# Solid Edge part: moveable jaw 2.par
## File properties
Author: CADSoft
Template: Normal.par
Last saved by: Cadcim
Revision: 5
Application: Solid Edge
Accuracy: 0.990
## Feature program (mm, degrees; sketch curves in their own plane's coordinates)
sketch for "unnamed Protrusion 1" plane through (0, 0, 0) normal (0, -1, 0) x-axis (1, 0, 0)
  line (2.077, -7.5) -> (2.077, 52.5)
  line (2.077, 52.5) -> (-32.423, 52.5)
  line (-32.423, 52.5) -> (-32.423, -7.5)
  line (-28.923, -7.5) -> (-32.423, -7.5)
  line (-28.923, -5) -> (-28.923, -7.5)
  line (-28.923, -5) -> (-26.423, -5)
  line (-26.423, -5) -> (-26.423, -2.5)
  line (-26.423, -2.5) -> (-23.923, -2.5)
  line (-23.923, -2.5) -> (-23.923, 0)
  line (-23.923, 0) -> (-21.423, 0)
  line (-21.423, 0) -> (-21.423, 2.5)
  line (-21.423, 2.5) -> (-18.923, 2.5)
  line (-18.923, 2.5) -> (-18.923, 5)
  line (-18.923, 5) -> (-16.423, 5)
  line (-16.423, 5) -> (-16.423, 7.5)
  line (-16.423, 7.5) -> (-15.173, 7.5)
  line (-13.923, 7.5) -> (-15.173, 7.5)
  line (-13.923, 5) -> (-13.923, 7.5)
  line (-11.423, 5) -> (-13.923, 5)
  line (-11.423, 2.5) -> (-11.423, 5)
  line (-8.923, 2.5) -> (-11.423, 2.5)
  line (-8.923, 0) -> (-8.923, 2.5)
  line (-6.423, 0) -> (-8.923, 0)
  line (-6.423, -2.5) -> (-6.423, 0)
  line (-3.923, -2.5) -> (-6.423, -2.5)
  line (-3.923, -5) -> (-3.923, -2.5)
  line (-1.423, -5) -> (-3.923, -5)
  line (-1.423, -5) -> (-1.423, -7.5)
  line (-1.423, -7.5) -> (2.077, -7.5)
extrude "unnamed Protrusion 1" add finite 18 symmetric
sketch for "Hole_1" plane through (-15.173, 0, 52.5) normal (0, 0, 1) x-axis (-1, 0, 0)
  hole centre (0, 0) bore radius 6
hole "Hole_1" diameter 12 finite  VBottomAngle = 120 deg
sketch for "Hole_2" plane through (2.077, 0, 22.5) normal (1, 0, 0) x-axis (0, 1, 0)
  hole centre (0, 23) bore radius 3
hole "Hole_2" diameter 6 through
chamfer "Chamfer_2" setback 2
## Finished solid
Body 1: solid body, 38 faces, 98 edges, 60 vertices.
  Faces by surface: plane 34, cylinder 3, cone 1
  Edges by curve: line 92, circle 4, intersection 2
Bounding box of the edges (mm): 34.500 x 18.000 x 60.000, from (-32.423, -9, -7.5) to (2.077, 9, 52.5).
Cylindrical faces by radius (mm): R3 x2, R6 x1
Conical faces (half-angle, radius in mm at the cone's reference point): 60 deg R6 x1
Planar faces by outward normal: +x 7, +y 1, +z 1, -x 7, -y 1, -z 13, oblique 4
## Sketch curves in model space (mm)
line (-26.423, 0, -5) -> (-26.423, 0, -2.5)
line (-26.423, 0, -2.5) -> (-23.923, 0, -2.5)
line (-23.923, 0, -2.5) -> (-23.923, 0, 0)
line (-23.923, 0, 0) -> (-21.423, 0, 0)
line (-21.423, 0, 0) -> (-21.423, 0, 2.5)
line (-21.423, 0, 2.5) -> (-18.923, 0, 2.5)
line (-18.923, 0, 2.5) -> (-18.923, 0, 5)
line (-18.923, 0, 5) -> (-16.423, 0, 5)
line (-16.423, 0, 5) -> (-16.423, 0, 7.5)
line (-16.423, 0, 7.5) -> (-15.173, 0, 7.5)
line (-13.923, 0, 7.5) -> (-15.173, 0, 7.5)
line (-13.923, 0, 5) -> (-13.923, 0, 7.5)
line (-11.423, 0, 5) -> (-13.923, 0, 5)
line (-11.423, 0, 2.5) -> (-11.423, 0, 5)
line (-8.923, 0, 2.5) -> (-11.423, 0, 2.5)
line (-8.923, 0, 0) -> (-8.923, 0, 2.5)
line (-6.423, 0, 0) -> (-8.923, 0, 0)
line (-6.423, 0, -2.5) -> (-6.423, 0, 0)
line (-3.923, 0, -2.5) -> (-6.423, 0, -2.5)
line (-3.923, 0, -5) -> (-3.923, 0, -2.5)
line (-1.423, 0, -5) -> (-3.923, 0, -5)
line (-1.423, 0, -5) -> (-1.423, 0, -7.5)
line (-1.423, 0, -7.5) -> (2.077, 0, -7.5)
line (2.077, 0, -7.5) -> (2.077, 0, 52.5)
line (2.077, 0, 52.5) -> (-32.423, 0, 52.5)
line (-32.423, 0, 52.5) -> (-32.423, 0, -7.5)
line (-28.923, 0, -7.5) -> (-32.423, 0, -7.5)
line (-28.923, 0, -5) -> (-28.923, 0, -7.5)
line (-28.923, 0, -5) -> (-26.423, 0, -5)
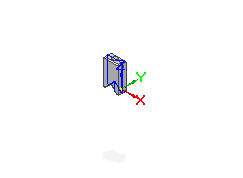
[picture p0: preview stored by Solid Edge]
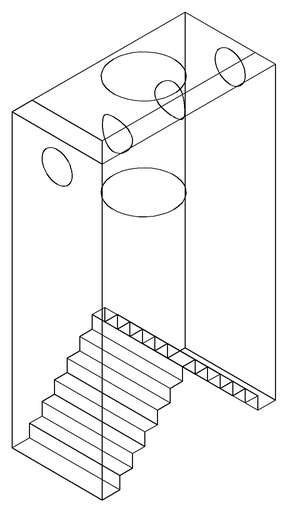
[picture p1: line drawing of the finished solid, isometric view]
